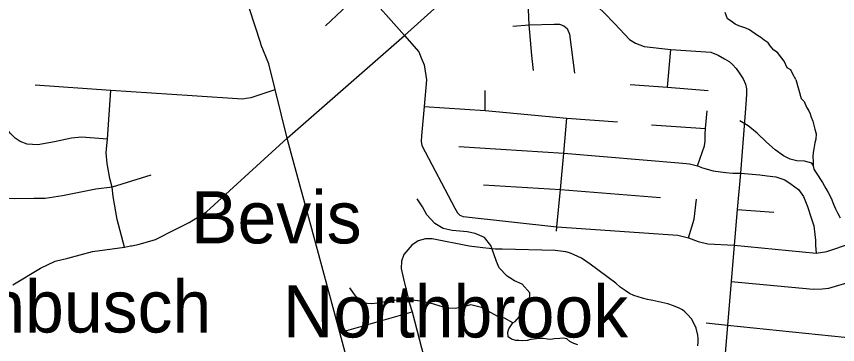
# Model space of a CAD drawing. Extents: x 0 to 34, y 0 to 22.
# Drawn here: x 3.515 to 4.758, y 17.102 to 17.598 of the extents above; entities that cross this region are included whole.
import ezdxf

# ---------------------------------------------------------------- set-up
doc = ezdxf.new("R2010")
doc.units = 0
for name, color, linetype in [('GM_X_County_Road', 7, 'Continuous'), ('GM_X_Minor_River', 7, 'Continuous'), ('GM_X_Township_Subdivision', 7, 'Continuous'), ('GM_X_Unincorporated_Text', 7, 'Continuous'), ('GM_X_US_Route', 7, 'Continuous')]:
    doc.layers.add(name, color=color, linetype=linetype)

msp = doc.modelspace()

# ---------------------------------------------------------------- linework, layer by layer
at = {"layer": 'GM_X_County_Road'}
for points in [[(3.9249, 17.4139), (4.1024, 17.5697), (4.2708, 17.7213), (4.2935, 17.7424), (4.3241, 17.7714), (4.3423, 17.7879), (4.3557, 17.8032), (4.3855, 17.8377), (4.3976, 17.8473), (4.4059, 17.853), (4.4167, 17.859), (4.4366, 17.8686), (4.4737, 17.8792), (4.6617, 17.9188), (4.7291, 17.933), (4.8264, 17.9531), (4.956, 17.9799), (5.1816, 18.0264), (5.2178, 18.0345), (5.2322, 18.0349), (5.2647, 18.0331), (5.4907, 18.0227), (5.5592, 18.0196)], [(3.6892, 17.2512), (3.6993, 17.2533), (3.7253, 17.2607), (3.7545, 17.2751), (3.7764, 17.2864), (3.8026, 17.3024), (3.9249, 17.4139)], [(3.5096, 17.192), (3.5513, 17.2174), (3.5735, 17.228), (3.5929, 17.2323), (3.6304, 17.2427), (3.6786, 17.249), (3.6876, 17.2509), (3.6892, 17.2512)]]:
    msp.add_lwpolyline(points, dxfattribs=at)
at = {"layer": 'GM_X_Minor_River'}
for points in [[(4.6947, 17.5031), (4.6903, 17.5108), (4.687, 17.5173), (4.6814, 17.5208), (4.677, 17.5304), (4.6733, 17.5351), (4.6667, 17.5436), (4.6614, 17.5475), (4.6559, 17.5537), (4.6525, 17.5583), (4.6469, 17.5622), (4.6417, 17.5665), (4.6368, 17.5693), (4.6245, 17.5779), (4.6188, 17.5807), (4.6083, 17.5843), (4.6026, 17.5867), (4.5966, 17.5914), (4.5914, 17.5945), (4.5878, 17.6041)], [(4.6947, 17.5031), (4.7028, 17.4743), (4.7072, 17.4696), (4.7108, 17.4608), (4.7141, 17.4557), (4.7162, 17.4507), (4.7176, 17.4457), (4.7201, 17.44), (4.7236, 17.4277), (4.7253, 17.4204), (4.7247, 17.4128), (4.7234, 17.4071), (4.722, 17.398), (4.7207, 17.3923), (4.7205, 17.3859), (4.7207, 17.3786), (4.7209, 17.3722), (4.7219, 17.3672), (4.7256, 17.3617), (4.7351, 17.347), (4.7401, 17.3381), (4.7438, 17.3319), (4.7481, 17.3234), (4.7517, 17.3142), (4.7545, 17.3072), (4.7578, 17.3011), (4.7618, 17.2937)], [(4.7209, 17.3732), (4.7188, 17.3762), (4.7079, 17.3795), (4.6961, 17.3798), (4.6859, 17.3823), (4.6762, 17.3871), (4.6631, 17.3962), (4.6501, 17.4079), (4.636, 17.4215), (4.6226, 17.4329), (4.6098, 17.4404)], [(4.2661, 17.1347), (4.2699, 17.1365), (4.2797, 17.148), (4.2818, 17.1579), (4.2916, 17.1679), (4.2919, 17.1797), (4.2804, 17.1929), (4.2688, 17.1981), (4.2579, 17.2052), (4.2457, 17.2177), (4.2414, 17.2273), (4.2375, 17.2388), (4.2332, 17.2518), (4.2236, 17.2635), (4.2093, 17.2699), (4.1972, 17.2725), (4.1862, 17.2731), (4.1745, 17.2742), (4.1609, 17.2772), (4.1485, 17.2851), (4.1363, 17.2979), (4.1294, 17.3103), (4.1217, 17.3223)], [(4.2661, 17.1347), (4.2537, 17.1418), (4.2435, 17.1443), (4.2334, 17.1499), (4.2188, 17.1579), (4.2029, 17.1617), (4.1914, 17.1589), (4.1792, 17.1562), (4.167, 17.1565), (4.1565, 17.1598), (4.1467, 17.1627), (4.1338, 17.166), (4.1225, 17.1678), (4.1085, 17.1693), (4.0955, 17.1692), (4.0833, 17.1676), (4.073, 17.1664), (4.062, 17.1644), (4.0524, 17.1631), (4.0396, 17.1645), (4.028, 17.1755), (4.0196, 17.1875)], [(4.2878, 17.1078), (4.2817, 17.1072), (4.2753, 17.1078), (4.2707, 17.1079), (4.2643, 17.11), (4.2594, 17.1131), (4.2589, 17.1204), (4.2605, 17.1253), (4.2633, 17.1302), (4.2661, 17.1347)], [(4.3648, 17.1014), (4.3584, 17.1035), (4.3524, 17.1064), (4.348, 17.1103), (4.343, 17.1112), (4.3373, 17.111), (4.3289, 17.1101), (4.324, 17.1091), (4.3187, 17.11), (4.3122, 17.1109), (4.3069, 17.1107), (4.2936, 17.1091), (4.2878, 17.1078)]]:
    msp.add_lwpolyline(points, dxfattribs=at)
at = {"layer": 'GM_X_Township_Subdivision'}
for points in [[(4.2693, 17.7229), (4.2708, 17.7213), (4.2901, 17.6981), (4.3117, 17.6741), (4.3192, 17.6665), (4.3355, 17.6543), (4.363, 17.6356), (4.3842, 17.6228), (4.4055, 17.6026), (4.4193, 17.5888), (4.4209, 17.587)], [(4.2976, 17.5167), (4.2953, 17.539), (4.2912, 17.5856), (4.2885, 17.6437), (4.2909, 17.6505), (4.2949, 17.6578), (4.3117, 17.6741), (4.319, 17.6813)], [(4.0411, 17.6387), (4.1024, 17.5697), (4.1239, 17.545), (4.1277, 17.5359), (4.1323, 17.5252), (4.1355, 17.5024), (4.1321, 17.4618), (4.1279, 17.4175), (4.1274, 17.4093), (4.1284, 17.4029), (4.1784, 17.3083), (4.1828, 17.3009), (4.186, 17.2975), (4.191, 17.2954), (4.3329, 17.28), (4.5161, 17.2672), (4.5322, 17.2634), (4.5467, 17.2577), (4.5616, 17.2543), (4.6015, 17.2519), (4.7252, 17.2398), (4.7414, 17.2423), (4.8149, 17.2674)], [(3.9828, 17.584), (4.0324, 17.631), (4.0324, 17.631)], [(4.2663, 17.5838), (4.2912, 17.5856), (4.3291, 17.5866), (4.3372, 17.5866), (4.3436, 17.5842), (4.3484, 17.58), (4.3519, 17.5715), (4.3596, 17.5126)], [(4.4209, 17.587), (4.4427, 17.5633), (4.452, 17.558), (4.465, 17.5528), (4.5055, 17.5485), (4.5659, 17.5443), (4.5771, 17.5399), (4.5868, 17.5344), (4.5935, 17.5302), (4.5986, 17.5258), (4.6041, 17.5195), (4.6091, 17.513), (4.6151, 17.5037), (4.6186, 17.4956), (4.6199, 17.4888), (4.6199, 17.4807), (4.619, 17.4653), (4.6107, 17.3612), (4.6057, 17.3062), (4.6015, 17.2519), (4.5968, 17.1971), (4.5912, 17.1311), (4.5874, 17.0821)], [(4.5004, 17.4913), (4.5055, 17.5485)], [(3.653, 17.4124), (3.6134, 17.4156), (3.5986, 17.4139), (3.5727, 17.4086), (3.5473, 17.4042), (3.5313, 17.4051), (3.5207, 17.4089), (3.5133, 17.4139), (3.5057, 17.4214), (3.4841, 17.4472), (3.4451, 17.4939), (3.4394, 17.5007), (3.4338, 17.5055), (3.4259, 17.5098), (3.4167, 17.5119), (3.3895, 17.5128)], [(3.5434, 17.4946), (3.6577, 17.4869), (3.7809, 17.4787), (3.8574, 17.4735), (3.8627, 17.4745), (3.8704, 17.4758), (3.9065, 17.488)], [(3.6786, 17.249), (3.6675, 17.2911), (3.6617, 17.3257), (3.6598, 17.3399), (3.6566, 17.3531), (3.6525, 17.3755), (3.6508, 17.3921), (3.6519, 17.403), (3.653, 17.4124), (3.6577, 17.4869)], [(4.2245, 17.4558), (4.2246, 17.486)], [(4.4437, 17.4952), (4.5004, 17.4913), (4.5621, 17.4862)], [(4.1321, 17.4618), (4.2245, 17.4558), (4.348, 17.4445), (4.4248, 17.4389)], [(4.5457, 17.3724), (4.5564, 17.4026), (4.5574, 17.4097), (4.5576, 17.42), (4.558, 17.4287), (4.5603, 17.4553)], [(4.3323, 17.2731), (4.3329, 17.28), (4.3387, 17.3366), (4.3433, 17.3914), (4.348, 17.4445)], [(4.4763, 17.4344), (4.558, 17.4287)], [(3.7187, 17.3581), (3.6598, 17.3399), (3.635, 17.337), (3.5849, 17.327), (3.5587, 17.3227), (3.5412, 17.3229), (3.5121, 17.3223), (3.4966, 17.3234), (3.4875, 17.3253), (3.4783, 17.3309), (3.4344, 17.3692), (3.4221, 17.3758), (3.4126, 17.378), (3.4031, 17.3813), (3.3968, 17.385), (3.3918, 17.3902), (3.3851, 17.3992), (3.378, 17.418)], [(4.1846, 17.4016), (4.3433, 17.3914), (4.5236, 17.3763), (4.5339, 17.375), (4.5457, 17.3724), (4.5536, 17.369), (4.5694, 17.3645), (4.5804, 17.3633), (4.5887, 17.3622), (4.5995, 17.3612), (4.6107, 17.3612), (4.6403, 17.3587), (4.6513, 17.357), (4.6646, 17.3554), (4.6778, 17.3509), (4.6877, 17.3445), (4.6986, 17.3363), (4.7063, 17.326), (4.7121, 17.3105), (4.718, 17.2934), (4.7219, 17.2813), (4.7234, 17.2681), (4.7244, 17.2597), (4.7242, 17.2518), (4.7252, 17.2398)], [(4.2218, 17.3433), (4.3387, 17.3366), (4.4897, 17.3245)], [(4.5322, 17.2634), (4.541, 17.2917), (4.5442, 17.3215)], [(4.6057, 17.3062), (4.6615, 17.3022)], [(4.2504, 17.246), (4.2399, 17.2463), (4.2209, 17.2479), (4.2, 17.2504), (4.1444, 17.2619), (4.1342, 17.2617), (4.1233, 17.2587), (4.1133, 17.2519), (4.1072, 17.2448), (4.1016, 17.2378), (4.098, 17.2281), (4.0972, 17.2166), (4.1007, 17.2009), (4.1059, 17.1806), (4.1093, 17.1652), (4.1138, 17.1512), (4.1464, 17.0268)], [(4.5465, 17.0999), (4.5469, 17.1055), (4.5469, 17.1107), (4.5462, 17.1161), (4.5438, 17.1265), (4.5411, 17.1322), (4.5366, 17.1404), (4.5309, 17.1471), (4.5267, 17.1511), (4.5231, 17.1541), (4.5182, 17.1567), (4.5097, 17.1605), (4.5007, 17.1631), (4.4784, 17.1682), (4.4699, 17.1699), (4.4628, 17.1718), (4.456, 17.1737), (4.4496, 17.1759), (4.4428, 17.1791), (4.4362, 17.1833), (4.4287, 17.1886), (4.4221, 17.1946), (4.3836, 17.2234), (4.37, 17.2325), (4.3593, 17.2376), (4.3523, 17.2406), (4.3466, 17.2419), (4.3304, 17.2438), (4.2504, 17.246)], [(4.5968, 17.1971), (4.7209, 17.1853), (4.7344, 17.1858), (4.7448, 17.1871), (4.7783, 17.1973)], [(4.0043, 17.1198), (4.1138, 17.1512)], [(4.5591, 17.1345), (4.5912, 17.1311), (4.788, 17.1107), (4.8481, 17.1037)]]:
    msp.add_lwpolyline(points, dxfattribs=at)
at = {"layer": 'GM_X_US_Route'}
for points in [[(3.8849, 17.5574), (3.8675, 17.6115), (3.8241, 17.7258), (3.8067, 17.7717), (3.7932, 17.8031), (3.7741, 17.8506), (3.7523, 17.9019), (3.721, 17.9807)], [(3.9249, 17.4139), (3.9065, 17.488), (3.897, 17.5267), (3.8857, 17.5548), (3.8849, 17.5574)], [(3.9324, 17.3858), (3.9274, 17.4045), (3.9249, 17.4139)], [(4.347, 15.8571), (4.343, 15.8718), (4.3094, 15.9915), (4.3082, 15.9958), (4.2961, 16.0399), (4.2826, 16.089), (4.2509, 16.204), (4.2124, 16.3441), (4.1884, 16.4342), (4.1794, 16.4679), (4.1431, 16.6089), (4.0889, 16.8066), (4.0359, 17.0028), (4.0043, 17.1198), (3.9604, 17.2824), (3.9324, 17.3858)]]:
    msp.add_lwpolyline(points, dxfattribs=at)

# ---------------------------------------------------------------- texts
at = {"layer": 'GM_X_Unincorporated_Text'}
for s, p in [('Bevis', (3.7792, 17.2548)), ('Dornbusch', (3.2992, 17.1199)), ('Northbrook', (3.9184, 17.1124))]:
    msp.add_text(s, height=0.07898, rotation=0, dxfattribs=at).set_placement(p)

doc.saveas('drawing.dxf')
